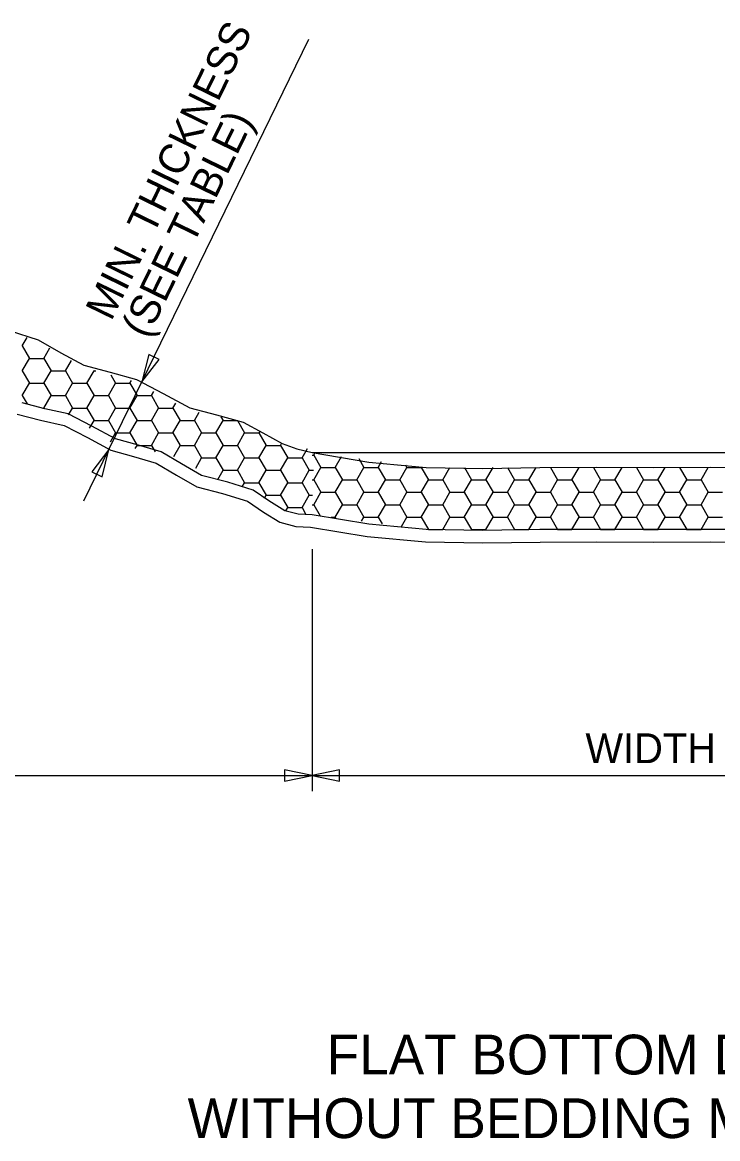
# Model space of a CAD drawing. Extents: x -439.1 to -407.9, y -458.1 to -436.2.
# Drawn here: x -431.12 to -427.62, y -446.22 to -440.61 of the extents above; entities that cross this region are included whole.
import ezdxf

# ---------------------------------------------------------------- set-up
doc = ezdxf.new("R2010")
doc.units = 0
doc.layers.add('Default', color=7, linetype='Continuous')

msp = doc.modelspace()

# ---------------------------------------------------------------- linework, layer by layer
at = {"layer": 'Default'}
for p, q in [((-430.8099, -443.0133), (-429.6786, -440.6916)), ((-431.1201, -442.2349), (-431.0952, -442.1919)), ((-431.1201, -442.2349), (-431.084, -442.2974)), ((-431.0118, -442.2974), (-430.9814, -442.2448)), ((-431.1201, -442.3599), (-431.084, -442.2974)), ((-431.084, -442.2974), (-431.0118, -442.2974)), ((-431.0118, -442.2974), (-430.9757, -442.3599)), ((-430.9036, -442.3599), (-430.8732, -442.3073)), ((-431.1201, -442.3599), (-431.084, -442.4224)), ((-431.0118, -442.4224), (-430.9757, -442.3599)), ((-430.9757, -442.3599), (-430.9036, -442.3599)), ((-430.9036, -442.3599), (-430.8675, -442.4224)), ((-430.7953, -442.4224), (-430.7592, -442.3599)), ((-430.7609, -442.3569), (-430.7592, -442.3599)), ((-430.7592, -442.3599), (-430.7502, -442.3599)), ((-431.1201, -442.4849), (-431.084, -442.4224)), ((-431.084, -442.4224), (-431.0118, -442.4224)), ((-431.0118, -442.4224), (-430.9757, -442.4849)), ((-430.9036, -442.4849), (-430.8675, -442.4224)), ((-430.8675, -442.4224), (-430.7953, -442.4224)), ((-430.7953, -442.4224), (-430.7592, -442.4849)), ((-430.687, -442.4849), (-430.651, -442.4224)), ((-430.6753, -442.3803), (-430.651, -442.4224)), ((-430.651, -442.4224), (-430.5788, -442.4224)), ((-430.5788, -442.4224), (-430.5709, -442.4087)), ((-430.5788, -442.4224), (-430.5427, -442.4849)), ((-431.1201, -442.4849), (-431.0961, -442.5264)), ((-431.0118, -442.5474), (-430.9757, -442.4849)), ((-430.9757, -442.4849), (-430.9036, -442.4849)), ((-430.9036, -442.4849), (-430.8675, -442.5474)), ((-430.7953, -442.5474), (-430.7592, -442.4849)), ((-430.7592, -442.4849), (-430.687, -442.4849)), ((-430.687, -442.4849), (-430.651, -442.5474)), ((-430.5788, -442.5474), (-430.5427, -442.4849)), ((-430.5427, -442.4849), (-430.4705, -442.4849)), ((-430.4705, -442.4849), (-430.4583, -442.4636)), ((-430.4705, -442.4849), (-430.4345, -442.5474)), ((-430.3623, -442.5474), (-430.3476, -442.5219)), ((-431.0168, -442.5474), (-431.0118, -442.5474)), ((-431.0118, -442.5474), (-431.0109, -442.5489)), ((-430.8873, -442.5817), (-430.8675, -442.5474)), ((-430.8675, -442.5474), (-430.7953, -442.5474)), ((-430.7953, -442.5474), (-430.7592, -442.6099)), ((-430.687, -442.6099), (-430.651, -442.5474)), ((-430.651, -442.5474), (-430.5788, -442.5474)), ((-430.5788, -442.5474), (-430.5427, -442.6099)), ((-430.4705, -442.6099), (-430.4345, -442.5474)), ((-430.4345, -442.5474), (-430.3623, -442.5474)), ((-430.3623, -442.5474), (-430.3262, -442.6099)), ((-430.254, -442.6099), (-430.2295, -442.5674)), ((-430.1208, -442.5907), (-430.1097, -442.6099)), ((-430.7814, -442.6483), (-430.7592, -442.6099)), ((-430.7592, -442.6099), (-430.687, -442.6099)), ((-430.687, -442.6099), (-430.651, -442.6724)), ((-430.5788, -442.6724), (-430.5427, -442.6099)), ((-430.5427, -442.6099), (-430.4705, -442.6099)), ((-430.4705, -442.6099), (-430.4345, -442.6724)), ((-430.3623, -442.6724), (-430.3262, -442.6099)), ((-430.3262, -442.6099), (-430.254, -442.6099)), ((-430.254, -442.6099), (-430.2179, -442.6724)), ((-430.1458, -442.6724), (-430.1097, -442.6099)), ((-430.1097, -442.6099), (-430.0375, -442.6099)), ((-430.0375, -442.6099), (-430.0368, -442.6087)), ((-430.0375, -442.6099), (-430.0014, -442.6724)), ((-430.6764, -442.7164), (-430.651, -442.6724)), ((-430.651, -442.6724), (-430.5788, -442.6724)), ((-430.5788, -442.6724), (-430.5427, -442.7349)), ((-430.4705, -442.7349), (-430.4345, -442.6724)), ((-430.4345, -442.6724), (-430.3623, -442.6724)), ((-430.3623, -442.6724), (-430.3262, -442.7349)), ((-430.254, -442.7349), (-430.2179, -442.6724)), ((-430.2179, -442.6724), (-430.1458, -442.6724)), ((-430.1458, -442.6724), (-430.1097, -442.7349)), ((-430.0375, -442.7349), (-430.0014, -442.6724)), ((-430.0014, -442.6724), (-429.9293, -442.6724)), ((-429.9293, -442.6724), (-429.9259, -442.6665)), ((-429.9293, -442.6724), (-429.8932, -442.7349)), ((-430.5517, -442.7504), (-430.5427, -442.7349)), ((-430.5427, -442.7349), (-430.4705, -442.7349)), ((-430.4705, -442.7349), (-430.4514, -442.7681)), ((-430.3583, -442.7905), (-430.3262, -442.7349)), ((-430.3262, -442.7349), (-430.254, -442.7349)), ((-430.254, -442.7349), (-430.2179, -442.7974)), ((-430.1458, -442.7974), (-430.1097, -442.7349)), ((-430.1097, -442.7349), (-430.0375, -442.7349)), ((-430.0375, -442.7349), (-430.0014, -442.7974)), ((-429.9293, -442.7974), (-429.8932, -442.7349)), ((-429.8932, -442.7349), (-429.821, -442.7349)), ((-429.821, -442.7349), (-429.8158, -442.7258)), ((-429.821, -442.7349), (-429.7849, -442.7974)), ((-429.7128, -442.7974), (-429.6861, -442.7512)), ((-430.2477, -442.8489), (-430.2179, -442.7974)), ((-430.2179, -442.7974), (-430.1458, -442.7974)), ((-430.1458, -442.7974), (-430.1097, -442.8599)), ((-430.0375, -442.8599), (-430.0014, -442.7974)), ((-430.0014, -442.7974), (-429.9293, -442.7974)), ((-429.9293, -442.7974), (-429.8932, -442.8599)), ((-429.821, -442.8599), (-429.7849, -442.7974)), ((-429.7849, -442.7974), (-429.7128, -442.7974)), ((-429.7128, -442.7974), (-429.6767, -442.8599)), ((-429.6624, -442.7704), (-426.2249, -442.7704)), ((-429.662, -442.7833), (-429.654, -442.7833)), ((-429.654, -442.7833), (-429.6479, -442.7727)), ((-429.654, -442.7833), (-429.6179, -442.8458)), ((-429.5458, -442.8458), (-429.5137, -442.7902)), ((-429.4269, -442.8016), (-429.4014, -442.8458)), ((-429.3293, -442.8458), (-429.3124, -442.8166)), ((-430.1361, -442.9057), (-430.1097, -442.8599)), ((-430.1097, -442.8599), (-430.0375, -442.8599)), ((-430.0375, -442.8599), (-430.0014, -442.9224)), ((-429.9293, -442.9224), (-429.8932, -442.8599)), ((-429.8932, -442.8599), (-429.821, -442.8599)), ((-429.821, -442.8599), (-429.7849, -442.9224)), ((-429.7128, -442.9224), (-429.6767, -442.8599)), ((-429.6767, -442.8599), (-429.6558, -442.8599)), ((-429.654, -442.9083), (-429.6179, -442.8458)), ((-429.6179, -442.8458), (-429.5458, -442.8458)), ((-429.5458, -442.8458), (-429.5097, -442.9083)), ((-429.4375, -442.9083), (-429.4014, -442.8458)), ((-429.4014, -442.8458), (-429.3293, -442.8458)), ((-429.3293, -442.8458), (-429.2932, -442.9083)), ((-429.221, -442.9083), (-429.1849, -442.8458)), ((-429.1927, -442.8322), (-429.1849, -442.8458)), ((-429.1849, -442.8458), (-429.1128, -442.8458)), ((-429.1128, -442.8458), (-429.1111, -442.8429)), ((-429.1128, -442.8458), (-429.0767, -442.9083)), ((-429.0045, -442.9083), (-428.9684, -442.8458)), ((-428.8962, -442.8458), (-428.8602, -442.9083)), ((-428.788, -442.9083), (-428.7519, -442.8458)), ((-428.6797, -442.8458), (-428.6437, -442.9083)), ((-428.5715, -442.9083), (-428.5354, -442.8458)), ((-428.4632, -442.8458), (-428.4272, -442.9083)), ((-428.355, -442.9083), (-428.3189, -442.8458)), ((-428.2467, -442.8458), (-428.2106, -442.9083)), ((-428.1385, -442.9083), (-428.1024, -442.8458)), ((-428.0302, -442.8458), (-427.9941, -442.9083)), ((-427.922, -442.9083), (-427.8859, -442.8458)), ((-427.8137, -442.8458), (-427.7776, -442.9083)), ((-427.7055, -442.9083), (-427.6694, -442.8458)), ((-430.0134, -442.9431), (-430.0014, -442.9224)), ((-430.0014, -442.9224), (-429.9293, -442.9224)), ((-429.9293, -442.9224), (-429.8932, -442.9849)), ((-429.821, -442.9849), (-429.7849, -442.9224)), ((-429.7849, -442.9224), (-429.7128, -442.9224)), ((-429.7128, -442.9224), (-429.6767, -442.9849)), ((-429.662, -442.9083), (-429.654, -442.9083)), ((-429.654, -442.9083), (-429.6179, -442.9708)), ((-429.5458, -442.9708), (-429.5097, -442.9083)), ((-429.5097, -442.9083), (-429.4375, -442.9083)), ((-429.4375, -442.9083), (-429.4014, -442.9708)), ((-429.3293, -442.9708), (-429.2932, -442.9083)), ((-429.2932, -442.9083), (-429.221, -442.9083)), ((-429.221, -442.9083), (-429.1849, -442.9708)), ((-429.1128, -442.9708), (-429.0767, -442.9083)), ((-429.0767, -442.9083), (-429.0045, -442.9083)), ((-429.0045, -442.9083), (-428.9684, -442.9708)), ((-428.8963, -442.9708), (-428.8602, -442.9083)), ((-428.8602, -442.9083), (-428.788, -442.9083)), ((-428.788, -442.9083), (-428.7519, -442.9708)), ((-428.6797, -442.9708), (-428.6437, -442.9083)), ((-428.6437, -442.9083), (-428.5715, -442.9083)), ((-428.5715, -442.9083), (-428.5354, -442.9708)), ((-428.4632, -442.9708), (-428.4272, -442.9083)), ((-428.4272, -442.9083), (-428.355, -442.9083)), ((-428.355, -442.9083), (-428.3189, -442.9708)), ((-428.2467, -442.9708), (-428.2106, -442.9083)), ((-428.2106, -442.9083), (-428.1385, -442.9083)), ((-428.1385, -442.9083), (-428.1024, -442.9708)), ((-428.0302, -442.9708), (-427.9941, -442.9083)), ((-427.9941, -442.9083), (-427.922, -442.9083)), ((-427.922, -442.9083), (-427.8859, -442.9708)), ((-427.8137, -442.9708), (-427.7776, -442.9083)), ((-427.7776, -442.9083), (-427.7055, -442.9083)), ((-427.7055, -442.9083), (-427.6694, -442.9708)), ((-429.9023, -443.0007), (-429.8932, -442.9849)), ((-429.8932, -442.9849), (-429.821, -442.9849)), ((-429.821, -442.9849), (-429.7849, -443.0474)), ((-429.7128, -443.0474), (-429.6767, -442.9849)), ((-429.6767, -442.9849), (-429.6593, -442.9849)), ((-429.654, -443.0333), (-429.6179, -442.9708)), ((-429.6179, -442.9708), (-429.5458, -442.9708)), ((-429.5458, -442.9708), (-429.5097, -443.0333)), ((-429.4375, -443.0333), (-429.4014, -442.9708)), ((-429.4014, -442.9708), (-429.3293, -442.9708)), ((-429.3293, -442.9708), (-429.2932, -443.0333)), ((-429.221, -443.0333), (-429.1849, -442.9708)), ((-429.1849, -442.9708), (-429.1128, -442.9708)), ((-429.1128, -442.9708), (-429.0767, -443.0333)), ((-429.0045, -443.0333), (-428.9684, -442.9708)), ((-428.9684, -442.9708), (-428.8963, -442.9708)), ((-428.8963, -442.9708), (-428.8602, -443.0333)), ((-428.788, -443.0333), (-428.7519, -442.9708)), ((-428.7519, -442.9708), (-428.6797, -442.9708)), ((-428.6797, -442.9708), (-428.6437, -443.0333)), ((-428.5715, -443.0333), (-428.5354, -442.9708)), ((-428.5354, -442.9708), (-428.4632, -442.9708)), ((-428.4632, -442.9708), (-428.4272, -443.0333)), ((-428.355, -443.0333), (-428.3189, -442.9708)), ((-428.3189, -442.9708), (-428.2467, -442.9708)), ((-428.2467, -442.9708), (-428.2106, -443.0333)), ((-428.1385, -443.0333), (-428.1024, -442.9708)), ((-428.1024, -442.9708), (-428.0302, -442.9708)), ((-428.0302, -442.9708), (-427.9941, -443.0333)), ((-427.922, -443.0333), (-427.8859, -442.9708)), ((-427.8859, -442.9708), (-427.8137, -442.9708)), ((-427.8137, -442.9708), (-427.7776, -443.0333)), ((-427.7055, -443.0333), (-427.6694, -442.9708)), ((-427.6694, -442.9708), (-427.5972, -442.9708)), ((-429.795, -443.0647), (-429.7849, -443.0474)), ((-429.7849, -443.0474), (-429.7128, -443.0474)), ((-429.7128, -443.0474), (-429.6947, -443.0787)), ((-429.662, -443.0333), (-429.654, -443.0333)), ((-429.654, -443.0333), (-429.6221, -443.0885)), ((-429.5458, -443.0958), (-429.5097, -443.0333)), ((-429.5097, -443.0333), (-429.4375, -443.0333)), ((-429.4375, -443.0333), (-429.4014, -443.0958)), ((-429.3293, -443.0958), (-429.2932, -443.0333)), ((-429.2932, -443.0333), (-429.221, -443.0333)), ((-429.221, -443.0333), (-429.1849, -443.0958)), ((-429.1128, -443.0958), (-429.0767, -443.0333)), ((-429.0767, -443.0333), (-429.0045, -443.0333)), ((-429.0045, -443.0333), (-428.9684, -443.0958)), ((-428.8963, -443.0958), (-428.8602, -443.0333)), ((-428.8602, -443.0333), (-428.788, -443.0333)), ((-428.788, -443.0333), (-428.7519, -443.0958)), ((-428.6797, -443.0958), (-428.6437, -443.0333)), ((-428.6437, -443.0333), (-428.5715, -443.0333)), ((-428.5715, -443.0333), (-428.5354, -443.0958)), ((-428.4632, -443.0958), (-428.4272, -443.0333)), ((-428.4272, -443.0333), (-428.355, -443.0333)), ((-428.355, -443.0333), (-428.3189, -443.0958)), ((-428.2467, -443.0958), (-428.2106, -443.0333)), ((-428.2106, -443.0333), (-428.1385, -443.0333)), ((-428.1385, -443.0333), (-428.1024, -443.0958)), ((-428.0302, -443.0958), (-427.9941, -443.0333)), ((-427.9941, -443.0333), (-427.922, -443.0333)), ((-427.922, -443.0333), (-427.8859, -443.0958)), ((-427.8137, -443.0958), (-427.7776, -443.0333)), ((-427.7776, -443.0333), (-427.7055, -443.0333)), ((-427.7055, -443.0333), (-427.6694, -443.0958)), ((-429.5667, -443.0958), (-429.5458, -443.0958)), ((-429.5458, -443.0958), (-429.5441, -443.0987)), ((-429.413, -443.1159), (-429.4014, -443.0958)), ((-429.4014, -443.0958), (-429.3293, -443.0958)), ((-429.3293, -443.0958), (-429.3098, -443.1294)), ((-429.2118, -443.1422), (-429.1849, -443.0958)), ((-429.1849, -443.0958), (-429.1128, -443.0958)), ((-429.1128, -443.0958), (-429.0767, -443.1583)), ((-429.0045, -443.1583), (-428.9684, -443.0958)), ((-428.9684, -443.0958), (-428.8963, -443.0958)), ((-428.8963, -443.0958), (-428.8602, -443.1583)), ((-428.788, -443.1583), (-428.7519, -443.0958)), ((-428.7519, -443.0958), (-428.6797, -443.0958)), ((-428.6797, -443.0958), (-428.6437, -443.1583)), ((-428.5715, -443.1583), (-428.5354, -443.0958)), ((-428.5354, -443.0958), (-428.4632, -443.0958)), ((-428.4632, -443.0958), (-428.4272, -443.1583)), ((-428.355, -443.1583), (-428.3189, -443.0958)), ((-428.3189, -443.0958), (-428.2467, -443.0958)), ((-428.2467, -443.0958), (-428.2106, -443.1583)), ((-428.1385, -443.1583), (-428.1024, -443.0958)), ((-428.1024, -443.0958), (-428.0302, -443.0958)), ((-428.0302, -443.0958), (-427.9941, -443.1583)), ((-427.922, -443.1583), (-427.8859, -443.0958)), ((-427.8859, -443.0958), (-427.8137, -443.0958)), ((-427.8137, -443.0958), (-427.7776, -443.1583)), ((-427.7055, -443.1583), (-427.6694, -443.0958)), ((-427.6694, -443.0958), (-427.5972, -443.0958)), ((-429.0767, -443.1583), (-429.0045, -443.1583)), ((-429.0767, -443.1583), (-429.0767, -443.1583)), ((-429.0045, -443.1583), (-429.0045, -443.1583)), ((-428.8602, -443.1583), (-428.788, -443.1583)), ((-428.8602, -443.1583), (-428.8602, -443.1583)), ((-428.788, -443.1583), (-428.788, -443.1583)), ((-428.6437, -443.1583), (-428.5715, -443.1583)), ((-428.6437, -443.1583), (-428.6437, -443.1583)), ((-428.5715, -443.1583), (-428.5715, -443.1583)), ((-428.4272, -443.1583), (-428.355, -443.1583)), ((-428.4272, -443.1583), (-428.4272, -443.1583)), ((-428.355, -443.1583), (-428.355, -443.1583)), ((-428.2107, -443.1583), (-428.2106, -443.1583)), ((-428.2106, -443.1583), (-428.1385, -443.1583)), ((-428.1385, -443.1583), (-428.1385, -443.1583)), ((-427.9942, -443.1583), (-427.9941, -443.1583)), ((-427.9941, -443.1583), (-427.922, -443.1583)), ((-427.922, -443.1583), (-427.9219, -443.1583)), ((-427.7777, -443.1583), (-427.7776, -443.1583)), ((-427.7776, -443.1583), (-427.7055, -443.1583)), ((-427.7055, -443.1583), (-427.7054, -443.1583)), ((-429.662, -443.2564), (-429.662, -444.4731)), ((-434.1025, -444.395), (-429.662, -444.395)), ((-429.662, -444.395), (-426.2245, -444.395))]:
    msp.add_line(p, q, dxfattribs=at)
for points in [[(-431.1864, -442.1576), (-431.0406, -442.2047), (-430.9258, -442.2694), (-430.8099, -442.3312), (-430.678, -442.3674), (-430.5458, -442.4031), (-430.4118, -442.4746), (-430.2776, -442.5458), (-430.1425, -442.5813), (-430.0084, -442.6187), (-429.9107, -442.6715), (-429.8131, -442.7259), (-429.7389, -442.7525), (-429.662, -442.7708)], [(-429.662, -443.0833), (-429.7324, -443.0808), (-429.8, -443.0639), (-429.8799, -443.0143), (-429.9578, -442.9607), (-430.0864, -442.9205), (-430.2179, -442.8858), (-430.3199, -442.827), (-430.4213, -442.7674), (-430.5361, -442.7336), (-430.652, -442.7016), (-430.77, -442.6375), (-430.8888, -442.5761), (-431.0062, -442.5503), (-431.1216, -442.5205)], [(-431.1465, -442.5778), (-431.0289, -442.6086), (-430.9093, -442.6352), (-430.7918, -442.6961), (-430.6751, -442.7597), (-430.5602, -442.7913), (-430.4464, -442.8247), (-430.3445, -442.8845), (-430.242, -442.9435), (-430.1131, -442.977), (-429.9871, -443.0159), (-429.9065, -443.0708), (-429.8239, -443.1216), (-429.7436, -443.1423), (-429.6696, -443.1454)], [(-429.662, -442.7708), (-429.3768, -442.8186), (-429.0891, -442.8458), (-428.8028, -442.8505), (-428.5161, -442.8458), (-428.2296, -442.8449), (-427.9432, -442.8458), (-427.6568, -442.8449), (-427.3703, -442.8458), (-427.0837, -442.8505), (-426.7974, -442.8458), (-426.5097, -442.8186), (-426.2245, -442.7708)], [(-426.2245, -443.0833), (-426.5097, -443.1311), (-426.7974, -443.1583), (-427.0837, -443.163), (-427.3703, -443.1583), (-427.6568, -443.1574), (-427.9432, -443.1583), (-428.2296, -443.1574), (-428.5161, -443.1583), (-428.8028, -443.163), (-429.0891, -443.1583), (-429.3768, -443.1311), (-429.662, -443.0833)], [(-429.6696, -443.1454), (-429.3845, -443.1931), (-429.0923, -443.2207), (-428.804, -443.2255), (-428.5153, -443.2208), (-428.2292, -443.2199), (-427.9432, -443.2208), (-427.6572, -443.2199), (-427.3711, -443.2208), (-427.0825, -443.2255), (-426.7941, -443.2207), (-426.502, -443.1931), (-426.2028, -443.143)]]:
    msp.add_lwpolyline(points, dxfattribs=at)
for points in [[(-430.4835, -442.2779), (-430.5183, -442.4148), (-430.4319, -442.303)], [(-430.4835, -442.2779), (-430.5183, -442.4148), (-430.4319, -442.303)], [(-430.719, -442.8922), (-430.6842, -442.7553), (-430.7706, -442.8671)], [(-430.719, -442.8922), (-430.6842, -442.7553), (-430.7706, -442.8671)], [(-429.8003, -444.4237), (-429.662, -444.395), (-429.8003, -444.3663)], [(-429.5237, -444.3663), (-429.662, -444.395), (-429.5237, -444.4237)]]:
    msp.add_lwpolyline(points, close=True, dxfattribs=at)

# ---------------------------------------------------------------- texts
for s, p in [('MIN. THICKNESS', (-430.6727, -442.1143)), ('(SEE TABLE)', (-430.4911, -442.2029))]:
    msp.add_text(s, height=0.15, rotation=64, dxfattribs=at).set_placement(p)
for s, height, p in [('WIDTH', 0.15, (-428.287, -444.3326)), ('FLAT BOTTOM DITCH', 0.2, (-429.5885, -445.898)), ('WITHOUT BEDDING MATERIAL', 0.2, (-430.2885, -446.218))]:
    msp.add_text(s, height=height, dxfattribs=at).set_placement(p)

doc.saveas('drawing.dxf')
